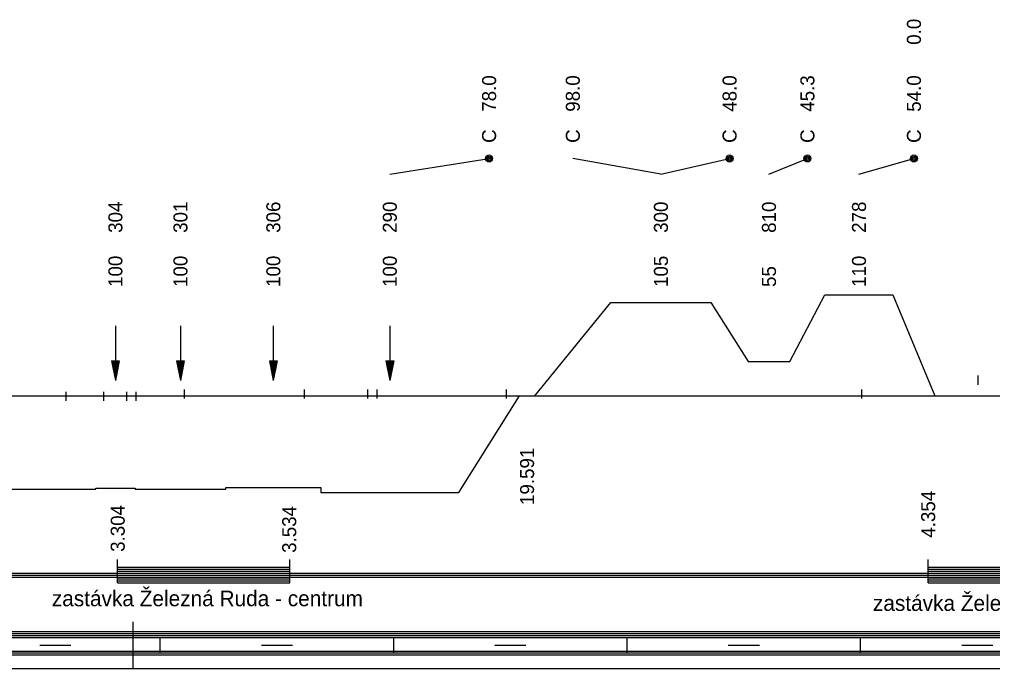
# Model space of a CAD drawing. Extents: x 2 to 10148, y 0 to 380.
# Drawn here: x 616.9 to 742, y 0 to 83.4 of the extents above; entities that cross this region are included whole.
import ezdxf

# ---------------------------------------------------------------- set-up
doc = ezdxf.new("R2010")
doc.units = 0
for name, color, linetype in [('KRIV1_CARA', 7, 'Continuous'), ('KRIV1_TEXT', 7, 'Continuous'), ('L_OBJEKTY_TEXT', 7, 'Continuous'), ('L_OBJEKTY_TVAR', 7, 'Continuous'), ('RAM', 7, 'Continuous'), ('STAN_CARA', 7, 'Continuous')]:
    doc.layers.add(name, color=color, linetype=linetype)

msp = doc.modelspace()

# ---------------------------------------------------------------- linework, layer by layer
for p, q in [((740.09, 37.61), (740.09, 36.42)), ((622.86, 35.55), (622.86, 34.36)), ((627.7, 35.55), (627.7, 34.36)), ((630.67, 35.55), (630.67, 34.36)), ((631.86, 35.55), (631.86, 34.36)), ((638.05, 35.85), (638.05, 34.66)), ((653.51, 35.85), (653.51, 34.66)), ((661.65, 35.85), (661.65, 34.66)), ((662.84, 35.85), (662.84, 34.66)), ((679.47, 35.85), (679.47, 34.66)), ((725.12, 35.85), (725.12, 34.66))]:
    msp.add_line(p, q)
at = {"layer": 'KRIV1_CARA'}
for p, q in [((715.9, 39.44), (720.43, 47.97)), ((720.43, 47.97), (729.16, 47.97)), ((729.16, 47.97), (734.56, 35)), ((683.12, 35), (692.92, 46.99)), ((692.92, 46.99), (705.77, 46.99)), ((705.77, 46.99), (710.57, 39.44)), ((710.57, 39.44), (715.9, 39.44)), ((301.52, 35), (632.74, 35)), ((631.22, 35), (1245.39, 35)), ((673.36, 22.6), (681.16, 35)), ((598.9, 23.04), (626.7, 23.04)), ((626.7, 23.04), (626.7, 23.16)), ((626.7, 23.16), (631.76, 23.16)), ((631.76, 23.16), (631.76, 23.04)), ((631.76, 23.04), (643.41, 23.04)), ((643.41, 23.04), (643.41, 23.24)), ((643.41, 23.24), (655.64, 23.24)), ((655.64, 23.24), (655.64, 22.6)), ((655.64, 22.6), (673.36, 22.6))]:
    msp.add_line(p, q, dxfattribs=at)
at = {"layer": 'KRIV1_TEXT'}
for p, q in [((664.5, 63.5), (677.26, 65.5)), ((699.34, 63.5), (688.02, 65.5)), ((699.34, 63.5), (708.17, 65.5)), ((713.23, 63.5), (718.17, 65.5)), ((724.8, 63.5), (731.86, 65.5)), ((629.23, 44), (629.23, 42.2)), ((637.59, 44), (637.59, 42.2)), ((649.53, 44), (649.53, 42.2)), ((664.5, 44), (664.5, 42.2)), ((629.23, 42.2), (629.23, 40)), ((637.59, 42.2), (637.59, 40)), ((649.53, 42.2), (649.53, 40)), ((664.5, 42.2), (664.5, 40)), ((628.73, 39.5), (629.23, 37)), ((628.73, 39.5), (629.73, 39.5)), ((628.83, 39.5), (629.23, 37.5)), ((628.93, 39.5), (629.23, 38)), ((629.03, 39.5), (629.23, 38.5)), ((629.13, 39.5), (629.23, 39)), ((629.23, 40), (629.23, 37)), ((629.73, 39.5), (629.23, 37)), ((629.63, 39.5), (629.23, 37.5)), ((629.53, 39.5), (629.23, 38)), ((629.43, 39.5), (629.23, 38.5)), ((629.33, 39.5), (629.23, 39)), ((629.23, 39.5), (629.23, 39.5)), ((629.23, 39.5), (629.23, 39.5)), ((637.09, 39.5), (637.59, 37)), ((637.09, 39.5), (638.09, 39.5)), ((637.19, 39.5), (637.59, 37.5)), ((637.29, 39.5), (637.59, 38)), ((637.39, 39.5), (637.59, 38.5)), ((637.49, 39.5), (637.59, 39)), ((637.59, 40), (637.59, 37)), ((638.09, 39.5), (637.59, 37)), ((637.99, 39.5), (637.59, 37.5)), ((637.89, 39.5), (637.59, 38)), ((637.79, 39.5), (637.59, 38.5)), ((637.69, 39.5), (637.59, 39)), ((637.59, 39.5), (637.59, 39.5)), ((637.59, 39.5), (637.59, 39.5)), ((649.03, 39.5), (649.53, 37)), ((649.03, 39.5), (650.03, 39.5)), ((649.13, 39.5), (649.53, 37.5)), ((649.23, 39.5), (649.53, 38)), ((649.33, 39.5), (649.53, 38.5)), ((649.43, 39.5), (649.53, 39)), ((649.53, 40), (649.53, 37)), ((650.03, 39.5), (649.53, 37)), ((649.93, 39.5), (649.53, 37.5)), ((649.83, 39.5), (649.53, 38)), ((649.73, 39.5), (649.53, 38.5)), ((649.63, 39.5), (649.53, 39)), ((649.53, 39.5), (649.53, 39.5)), ((649.53, 39.5), (649.53, 39.5)), ((664, 39.5), (664.5, 37)), ((664, 39.5), (665, 39.5)), ((664.1, 39.5), (664.5, 37.5)), ((664.2, 39.5), (664.5, 38)), ((664.3, 39.5), (664.5, 38.5)), ((664.4, 39.5), (664.5, 39)), ((664.5, 40), (664.5, 37)), ((665, 39.5), (664.5, 37)), ((664.9, 39.5), (664.5, 37.5)), ((664.8, 39.5), (664.5, 38)), ((664.7, 39.5), (664.5, 38.5)), ((664.6, 39.5), (664.5, 39)), ((664.5, 39.5), (664.5, 39.5)), ((664.5, 39.5), (664.5, 39.5))]:
    msp.add_line(p, q, dxfattribs=at)
for centre, radius in [((677.26, 65.5), 0.45), ((677.26, 65.5), 0.3), ((677.26, 65.5), 0.15), ((708.17, 65.5), 0.45), ((708.17, 65.5), 0.3), ((708.17, 65.5), 0.15), ((718.17, 65.5), 0.45), ((718.17, 65.5), 0.3), ((718.17, 65.5), 0.15), ((731.86, 65.5), 0.45), ((731.86, 65.5), 0.3), ((731.86, 65.5), 0.15)]:
    msp.add_circle(centre, radius, dxfattribs=at)
at = {"layer": 'L_OBJEKTY_TVAR'}
for p, q in [((629.5, 11), (629.5, 14)), ((651.65, 11), (651.65, 14)), ((733.69, 11), (733.69, 14)), ((629.5, 13), (651.65, 13)), ((629.5, 12.75), (651.65, 12.75)), ((733.69, 13), (756.16, 13)), ((733.69, 12.75), (756.16, 12.75)), ((629.5, 12.5), (632.74, 12.5)), ((629.5, 11.5), (651.65, 11.5)), ((631.22, 12.5), (651.65, 12.5)), ((631.22, 12.25), (651.65, 12.25)), ((631.22, 12), (651.65, 12)), ((631.22, 11.75), (651.65, 11.75)), ((733.69, 12.5), (756.16, 12.5)), ((733.69, 12.25), (756.16, 12.25)), ((733.69, 12), (756.16, 12)), ((733.69, 11.75), (756.16, 11.75)), ((733.69, 11.5), (756.16, 11.5)), ((629.5, 11.25), (651.65, 11.25)), ((629.5, 11), (651.65, 11)), ((733.69, 11.25), (756.16, 11.25)), ((733.69, 11), (756.16, 11))]:
    msp.add_line(p, q, dxfattribs=at)
at = {"layer": 'RAM'}
for p, q in [((631.52, 0), (631.52, 6)), ((5.52, 4.75), (632.74, 4.75)), ((5.52, 4.5), (632.74, 4.5)), ((5.52, 4.25), (632.74, 4.25)), ((5.52, 4), (632.74, 4)), ((631.22, 4.75), (1245.39, 4.75)), ((631.22, 4.5), (1245.39, 4.5)), ((631.22, 4.25), (1245.39, 4.25)), ((631.22, 4), (1245.39, 4)), ((635, 2), (635, 4)), ((665, 2), (665, 4)), ((695, 2), (695, 4)), ((725, 2), (725, 4)), ((619.52, 3), (623.52, 3)), ((648, 3), (652, 3)), ((678, 3), (682, 3)), ((708, 3), (712, 3)), ((738, 3), (742, 3)), ((3.52, 2.25), (632.74, 2.25)), ((3.52, 2), (632.74, 2)), ((3.52, 1.75), (632.74, 1.75)), ((631.22, 2.25), (1245.39, 2.25)), ((631.22, 2), (1245.39, 2)), ((631.22, 1.75), (1245.39, 1.75)), ((1.52, 0), (632.74, 0)), ((631.22, 0), (1245.39, 0))]:
    msp.add_line(p, q, dxfattribs=at)
at = {"layer": 'STAN_CARA'}
for p, q in [((301.52, 12.25), (632.74, 12.25)), ((301.52, 12), (632.74, 12)), ((301.52, 12), (632.74, 12)), ((301.52, 11.75), (632.74, 11.75)), ((631.22, 12.25), (796.79, 12.25)), ((631.22, 12), (796.79, 12)), ((631.22, 12), (796.79, 12)), ((631.22, 11.75), (796.79, 11.75))]:
    msp.add_line(p, q, dxfattribs=at)

# ---------------------------------------------------------------- texts
at = {"layer": 'KRIV1_TEXT'}
for s, p in [('0.0', (732.76, 80.1)), ('78.0', (678.16, 71.5)), ('98.0', (688.92, 71.5)), ('48.0', (709.07, 71.5)), ('45.3', (719.07, 71.5)), ('54.0', (732.76, 71.5)), ('C', (678.16, 67.5)), ('C', (688.92, 67.5)), ('C', (709.07, 67.5)), ('C', (719.07, 67.5)), ('C', (732.76, 67.5)), ('304', (630.13, 55.95)), ('301', (638.49, 55.95)), ('306', (650.43, 55.95)), ('290', (665.4, 55.95)), ('300', (700.24, 55.95)), ('810', (714.13, 55.95)), ('278', (725.7, 55.95)), ('100', (630.13, 49)), ('100', (638.49, 49)), ('100', (650.43, 49)), ('100', (665.4, 49)), ('105', (700.24, 49)), ('110', (725.7, 49)), ('55', (714.13, 49)), ('19.591', (683.04, 21))]:
    msp.add_text(s, height=1.8, rotation=90, dxfattribs=at).set_placement(p)
at = {"layer": 'L_OBJEKTY_TEXT'}
for s, p in [('4.354', (734.59, 16.8)), ('3.304', (630.43, 14.98)), ('3.534', (652.47, 14.85))]:
    msp.add_text(s, height=1.8, rotation=90, dxfattribs=at).set_placement(p)
for s, p in [('zastávka Železná Ruda - centrum', (621.06, 8)), ('zastávka Železná Ruda - město', (726.59, 7.4))]:
    msp.add_text(s, height=2, dxfattribs=at).set_placement(p)

doc.saveas('drawing.dxf')
